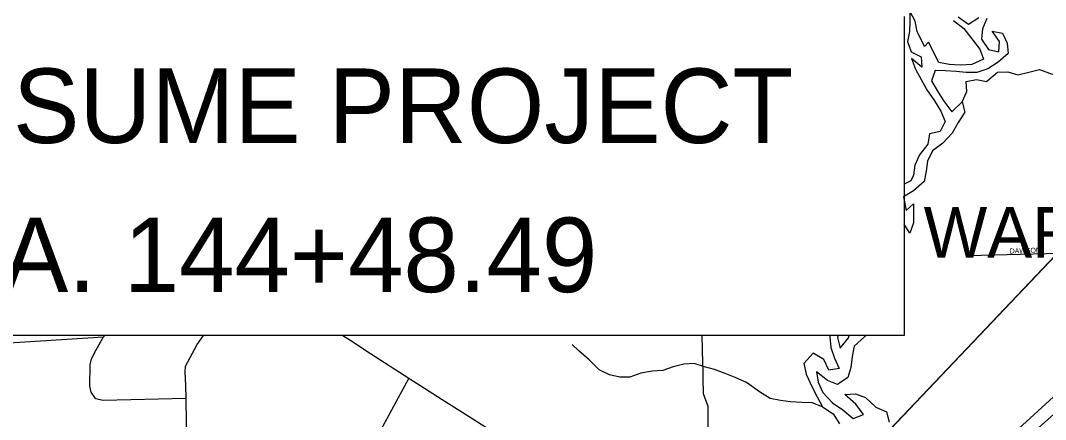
# Model space of a CAD drawing. Extents: x -37878.7 to -37844.7, y -19791.4 to -19769.4.
# Drawn here: x -37873.927 to -37872, y -19773.183 to -19772.434 of the extents above; entities that cross this region are included whole.
import ezdxf

# ---------------------------------------------------------------- set-up
doc = ezdxf.new("R2010")
doc.units = 0
for name, color, linetype in [('GM_X_City_Street', 7, 'Continuous'), ('GM_X_Corporation_Text', 7, 'Continuous'), ('GM_X_County_Road', 7, 'Continuous'), ('GM_X_Major_River', 7, 'Continuous'), ('GM_X_Minor_River', 7, 'Continuous'), ('GM_X_Township_Subdivision', 7, 'Continuous'), ('GM_X_Township_Subdivision_Text', 7, 'Continuous'), ('GM_X_US_Route', 7, 'Continuous'), ('TX_P_1', 7, 'Continuous')]:
    doc.layers.add(name, color=color, linetype=linetype)

msp = doc.modelspace()

# ---------------------------------------------------------------- linework, layer by layer
at = {"layer": 'GM_X_City_Street'}
for points in [[(-37874.243, -19773.0455), (-37874.2367, -19773.0452), (-37874.0939, -19773.0438), (-37873.9584, -19773.0393), (-37873.7706, -19773.0279)], [(-37873.7858, -19773.1436), (-37873.7942, -19773.1315), (-37873.7963, -19773.12), (-37873.7958, -19773.08), (-37873.7932, -19773.069), (-37873.7848, -19773.0521), (-37873.7706, -19773.0279), (-37873.7684, -19773.0251)], [(-37873.612, -19773.3576), (-37873.6127, -19773.3304), (-37873.6154, -19773.1426), (-37873.6163, -19773.1186), (-37873.6172, -19773.0939), (-37873.6169, -19773.0825), (-37873.5946, -19773.0418), (-37873.583, -19773.0251)], [(-37872.6407, -19773.1416), (-37872.6433, -19773.1347), (-37872.6435, -19773.1054), (-37872.6436, -19773.1018)], [(-37873.7858, -19773.1436), (-37873.7716, -19773.1468), (-37873.6154, -19773.1426)]]:
    msp.add_lwpolyline(points, dxfattribs=at)
at = {"layer": 'GM_X_County_Road'}
for points in [[(-37872.6448, -19773.0514), (-37872.6456, -19773.0251)], [(-37872.6436, -19773.1018), (-37872.6437, -19773.0912), (-37872.6447, -19773.055), (-37872.6448, -19773.0514)], [(-37872.6344, -19773.1707), (-37872.6345, -19773.1583), (-37872.6407, -19773.1416)], [(-37872.6343, -19773.1807), (-37872.6344, -19773.1707)], [(-37872.6341, -19773.2009), (-37872.6343, -19773.1807)]]:
    msp.add_lwpolyline(points, dxfattribs=at)
at = {"layer": 'GM_X_Major_River'}
for points in [[(-37872.1732, -19772.4336), (-37872.1539, -19772.4488), (-37872.1387, -19772.4678), (-37872.1236, -19772.4872), (-37872.1171, -19772.5064), (-37872.1385, -19772.516), (-37872.1608, -19772.5172), (-37872.1813, -19772.5162), (-37872.2007, -19772.5124), (-37872.2204, -19772.4743), (-37872.2278, -19772.4824), (-37872.2417, -19772.4544), (-37872.2451, -19772.4351), (-37872.255, -19772.416), (-37872.2554, -19772.435), (-37872.2561, -19772.454), (-37872.2595, -19772.473), (-37872.253, -19772.4922), (-37872.2339, -19772.5021), (-37872.2327, -19772.521), (-37872.252, -19772.5051), (-37872.2448, -19772.5247), (-37872.2338, -19772.5442), (-37872.2235, -19772.5637), (-37872.2087, -19772.5843), (-37872.1969, -19772.6038), (-37872.1889, -19772.623), (-37872.1984, -19772.6422), (-37872.2184, -19772.6464), (-37872.2214, -19772.6658), (-37872.2369, -19772.6859), (-37872.2456, -19772.7051), (-37872.2482, -19772.7241)], [(-37872.1107, -19772.4296), (-37872.119, -19772.4495), (-37872.1209, -19772.4686), (-37872.1076, -19772.488), (-37872.0878, -19772.4925), (-37872.0867, -19772.4731), (-37872.1004, -19772.4537), (-37872.0814, -19772.4571), (-37872.0723, -19772.4762), (-37872.0704, -19772.4956), (-37872.0893, -19772.5119), (-37872.1084, -19772.5245), (-37872.1291, -19772.531), (-37872.1495, -19772.5314), (-37872.1685, -19772.5292), (-37872.1886, -19772.5281), (-37872.2076, -19772.5273), (-37872.2148, -19772.5469), (-37872.203, -19772.566), (-37872.1912, -19772.5851), (-37872.1764, -19772.6049), (-37872.1571, -19772.5862), (-37872.1518, -19772.6055), (-37872.1646, -19772.6251), (-37872.1756, -19772.6451), (-37872.1934, -19772.6641), (-37872.2128, -19772.6782), (-37872.2222, -19772.6977), (-37872.2249, -19772.7168), (-37872.2286, -19772.7358), (-37872.2484, -19772.7533), (-37872.2674, -19772.7648), (-37872.2625, -19772.7903), (-37872.2487, -19772.7777), (-37872.2486, -19772.8133), (-37872.255, -19772.8328), (-37872.2662, -19772.8158)], [(-37872.1642, -19772.4266), (-37872.145, -19772.4402), (-37872.1259, -19772.428)], [(-37872.2482, -19772.7241), (-37872.2537, -19772.7345), (-37872.2657, -19772.7408), (-37872.2662, -19772.7414)], [(-37872.4054, -19773.0251), (-37872.4059, -19773.0277), (-37872.404, -19773.0474), (-37872.3971, -19773.0678), (-37872.3884, -19773.0874), (-37872.4077, -19773.09), (-37872.4168, -19773.0701), (-37872.4367, -19773.0584), (-37872.4545, -19773.0778), (-37872.4503, -19773.0978), (-37872.4396, -19773.1207), (-37872.4297, -19773.1402), (-37872.4195, -19773.1594), (-37872.3995, -19773.1722), (-37872.3874, -19773.1913)], [(-37872.3371, -19773.0251), (-37872.3404, -19773.0279), (-37872.3601, -19773.0454), (-37872.3635, -19773.0644), (-37872.3661, -19773.085), (-37872.3718, -19773.1041), (-37872.3912, -19773.1174), (-37872.4103, -19773.1098), (-37872.4307, -19773.0932), (-37872.4273, -19773.1125), (-37872.4189, -19773.132), (-37872.4007, -19773.1518), (-37872.3815, -19773.165)], [(-37872.3903, -19773.0251), (-37872.3911, -19773.0286), (-37872.3865, -19773.049), (-37872.3707, -19773.0293), (-37872.3691, -19773.0251)], [(-37872.3815, -19773.165), (-37872.3618, -19773.1809), (-37872.3427, -19773.1733), (-37872.3567, -19773.1539), (-37872.3772, -19773.1357), (-37872.3575, -19773.1345), (-37872.3384, -19773.1417), (-37872.3191, -19773.1595), (-37872.2992, -19773.1682), (-37872.2942, -19773.1878)]]:
    msp.add_lwpolyline(points, dxfattribs=at)
at = {"layer": 'GM_X_Minor_River'}
for points in [[(-37872.1571, -19772.5862), (-37872.1484, -19772.5671), (-37872.1492, -19772.5481), (-37872.13, -19772.5443), (-37872.1109, -19772.5484), (-37872.0908, -19772.5309), (-37872.0711, -19772.5301), (-37872.0521, -19772.5358), (-37872.0314, -19772.5304), (-37872.0118, -19772.5254), (-37871.9927, -19772.5326), (-37871.9744, -19772.5379)], [(-37872.4195, -19773.1594), (-37872.439, -19773.1518), (-37872.4583, -19773.1507), (-37872.4795, -19773.15), (-37872.4985, -19773.1474), (-37872.5176, -19773.1433), (-37872.5379, -19773.1308), (-37872.5621, -19773.1131), (-37872.5835, -19773.104), (-37872.6026, -19773.0965), (-37872.6225, -19773.0893), (-37872.6415, -19773.084), (-37872.6606, -19773.078), (-37872.6803, -19773.0792), (-37872.7002, -19773.0841), (-37872.7198, -19773.091), (-37872.7399, -19773.0922), (-37872.7606, -19773.0957), (-37872.7813, -19773.1033), (-37872.8006, -19773.1034), (-37872.8197, -19773.0992), (-37872.8392, -19773.0898), (-37872.8581, -19773.0708), (-37872.8774, -19773.0538), (-37872.8902, -19773.0419)]]:
    msp.add_lwpolyline(points, dxfattribs=at)
at = {"layer": 'GM_X_Township_Subdivision'}
for points in [[(-37871.7188, -19772.8683), (-37871.7257, -19772.8692), (-37871.9005, -19772.8691), (-37872.1457, -19772.8754)], [(-37873.1969, -19773.1051), (-37873.311, -19773.3154), (-37873.311, -19773.3268), (-37873.3111, -19773.389), (-37873.3113, -19773.4517)]]:
    msp.add_lwpolyline(points, dxfattribs=at)
at = {"layer": 'GM_X_US_Route'}
for points in [[(-37873.321, -19773.0251), (-37873.3107, -19773.0317)], [(-37873.3107, -19773.0317), (-37873.3058, -19773.0348), (-37873.2687, -19773.0588)], [(-37873.2687, -19773.0588), (-37873.1969, -19773.1051), (-37873.1931, -19773.1075)], [(-37873.1931, -19773.1075), (-37873.1762, -19773.1183)], [(-37873.1762, -19773.1183), (-37873.134, -19773.1451)], [(-37873.134, -19773.1451), (-37873.0834, -19773.1773)], [(-37873.0834, -19773.1773), (-37873.0159, -19773.2202)]]:
    msp.add_lwpolyline(points, dxfattribs=at)
at = {"layer": 'TX_P_1'}
for p, q in [((-37872.2662, -19772.4261), (-37872.2662, -19773.0251)), ((-37871.7188, -19772.5985), (-37873.8226, -19774.8103)), ((-37873.8226, -19774.8103), (-37871.7188, -19772.898)), ((-37872.2662, -19773.0251), (-37874.245, -19773.0251))]:
    msp.add_line(p, q, dxfattribs=at)
msp.add_lwpolyline([(-37871.7188, -19772.5985), (-37873.8226, -19774.8103), (-37871.7188, -19772.9363)], close=True, dxfattribs=at)

# ---------------------------------------------------------------- texts
at = {"layer": 'GM_X_Corporation_Text'}
msp.add_text('WARREN', height=0.0947, rotation=0, dxfattribs=at).set_placement((-37872.2293, -19772.8787))
at = {"layer": 'GM_X_Township_Subdivision_Text'}
msp.add_text('DAWSON', height=0.00947, rotation=1.8769, dxfattribs=at).set_placement((-37872.0676, -19772.8713))
at = {"layer": 'TX_P_1'}
for s, p in [('RESUME PROJECT', (-37874.201, -19772.6637)), ('STA. 144+48.49', (-37874.201, -19772.9437))]:
    msp.add_text(s, height=0.14, rotation=360, dxfattribs=at).set_placement(p)

doc.saveas('drawing.dxf')
